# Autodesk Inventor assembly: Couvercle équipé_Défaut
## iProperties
Shininess: 64.0
Length Units: 11269
Angle Units: 11279
Time Units: 11290
Mass Units: 11283
Length Display Precision: 3
Angle Display Precision: 2
Compacted: True
Created: 2006-01
Part Number: Couvercle équipé_Défaut
Document SubType Name: Assembly
Designer: riri
Density: 0.0
Volumn: 0.0
Area: 0.0
PropertySet Name: Model Information
Control State: 0
Master: False
Checked Out: False
Author: riri
